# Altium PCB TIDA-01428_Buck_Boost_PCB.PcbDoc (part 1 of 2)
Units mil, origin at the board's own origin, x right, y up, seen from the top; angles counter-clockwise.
Board outline 4000 x 3000 mil, 2 copper layers (Top Layer, Bottom Layer), stack 62 mil thick; 127 components, 76 nets, 360 pads, 338 vias.
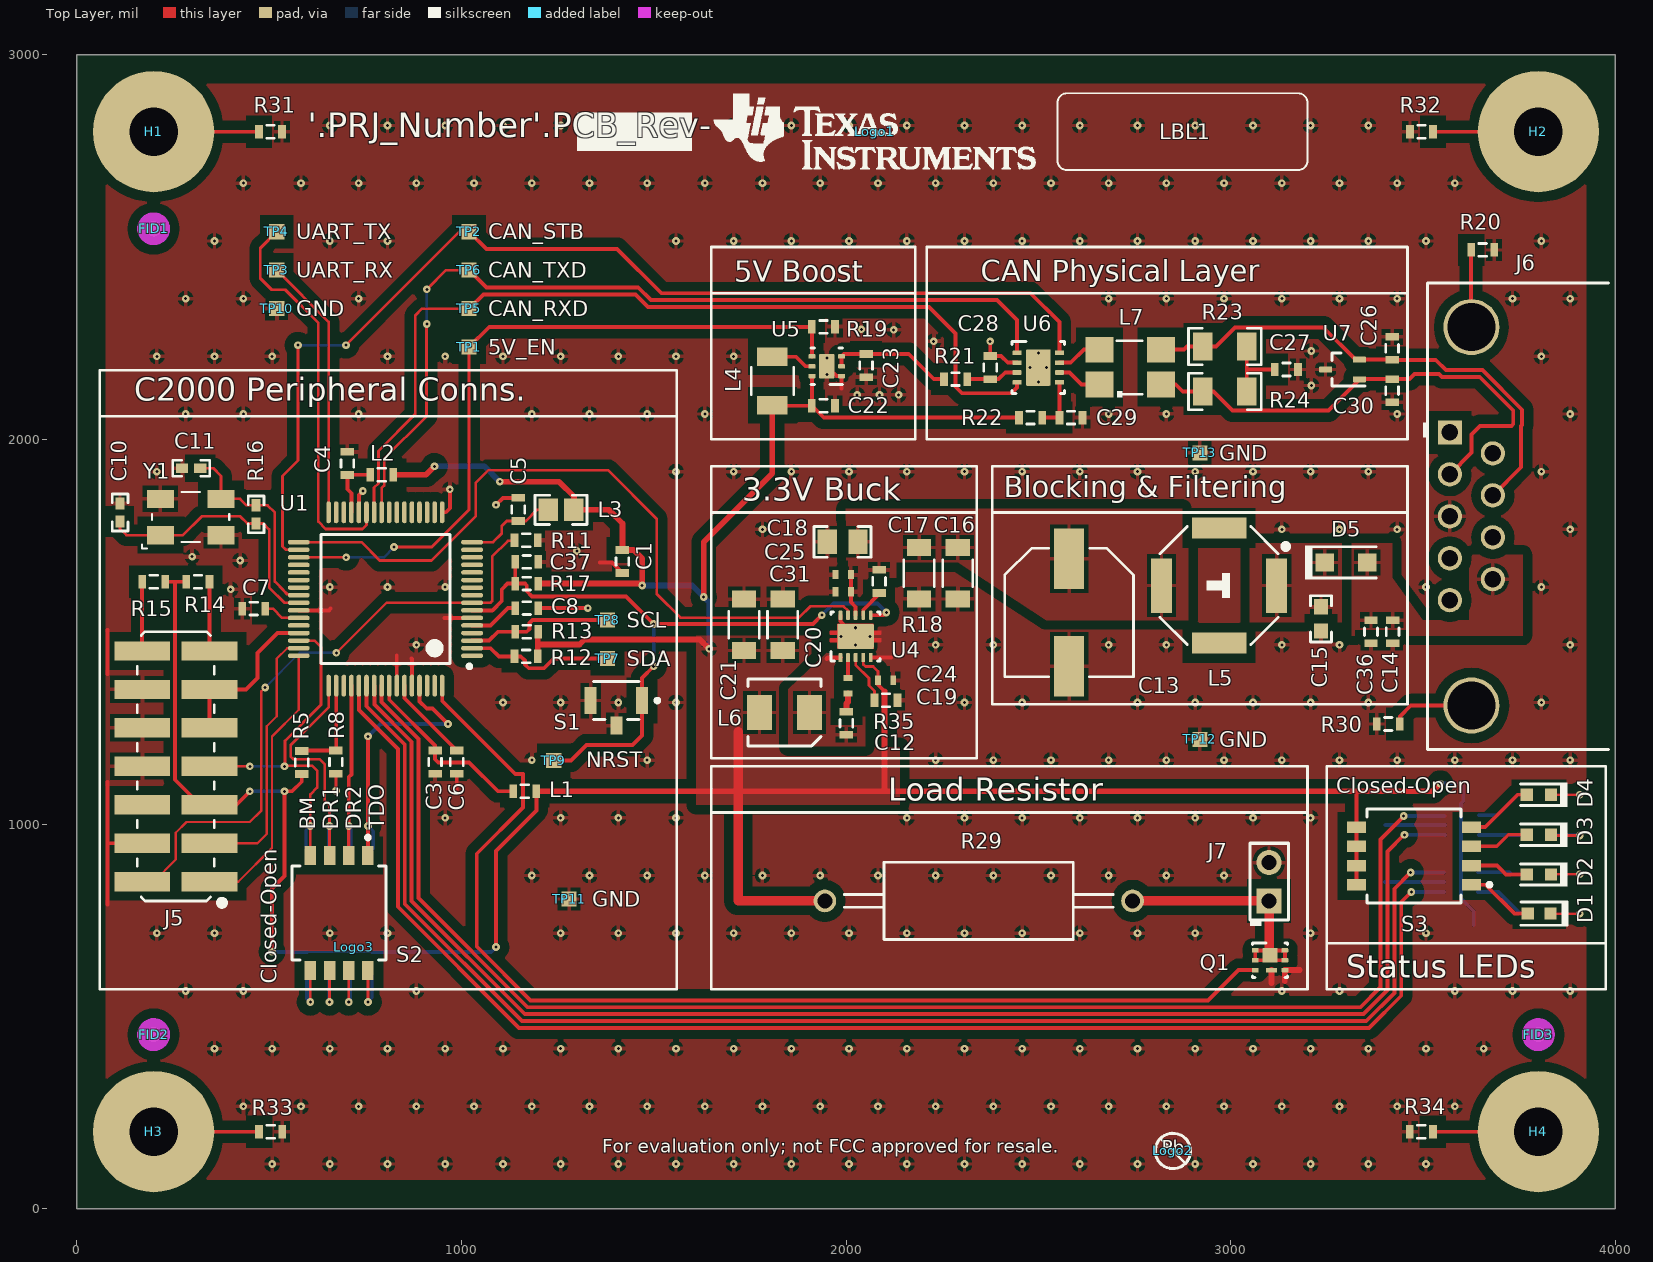
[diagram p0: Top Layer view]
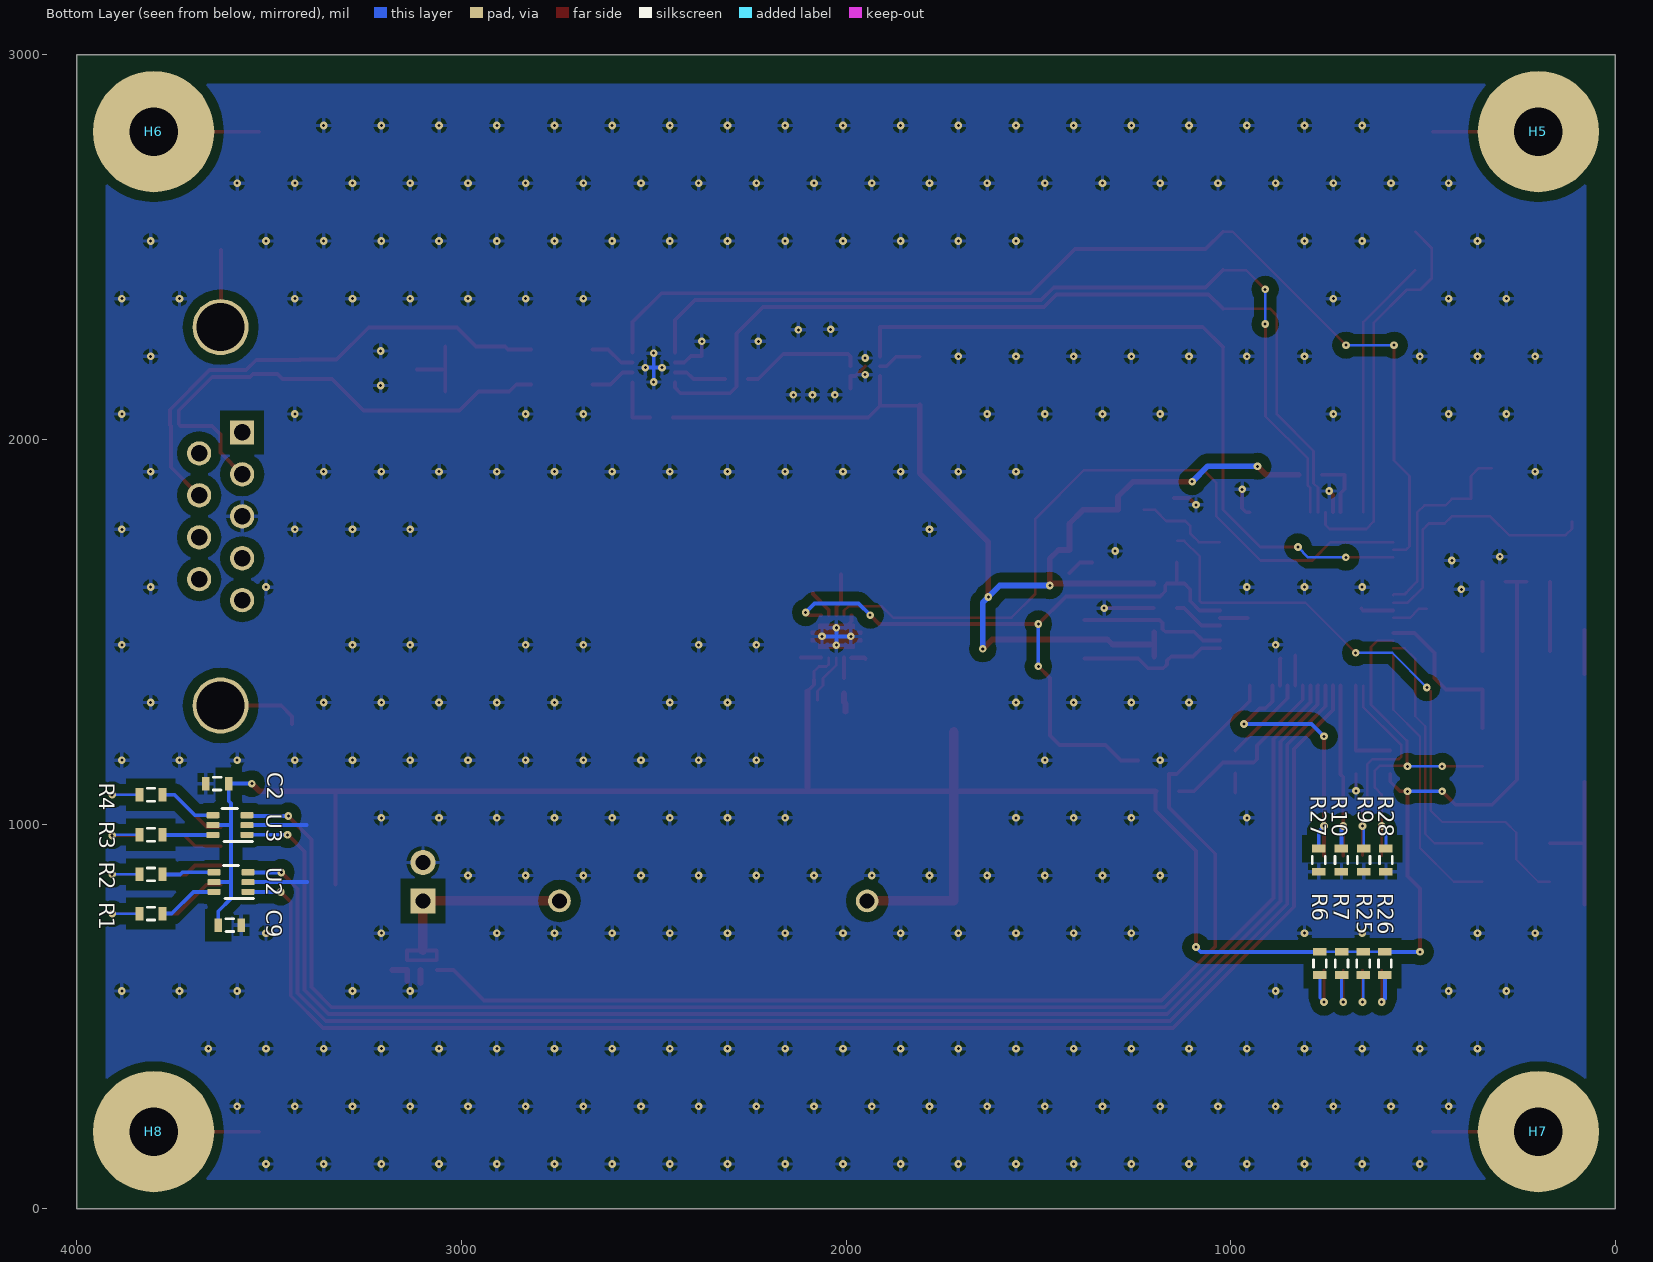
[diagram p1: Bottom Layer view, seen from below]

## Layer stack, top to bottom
Top Solder: solder mask 0.4, Solder Resist, Dk 3.5
Top Layer: signal copper 1.4
Dielectric1: core 59.2, FR-4, Dk 4.8
Bottom Layer: signal copper 1.4
Bottom Solder: solder mask 0.4, Solder Resist, Dk 3.5

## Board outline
0,0 0,3000 4000,3000 4000,0

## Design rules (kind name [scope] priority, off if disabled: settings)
AcuteAngle [All] p1: minimum=4.50000000000000E+0001 checktracksonly=FALSE
AssemblyTestPointUsage [All] p1: valid=2
BoardOutlineClearance BoardOutlineClearance_MountingHoles [OnCopper and InComponentClass('Mounting Holes')] p1: gap=40
BoardOutlineClearance BoardOutlineClearance_Poly [OnCopper and IsPoly] p2: gap=25
BoardOutlineClearance [OnCopper and Not InComponentClass('Logo') and not InComponentClass('FiducialMark') and not InRegion(1000,500,4000,800) and not InPoly] p3: gap=75
Clearance Clearance_Keepouts [((IsTrack Or IsArc) And Not InPoly) And IsFree and IsKeepOut vs ((IsTrack Or IsArc) And Not InPoly) And IsFree and IsKeepOut] p1: gap=0
Clearance Clearance_Poly [InPolygon] p2: gap=25 except(20: Fill-Fill)
Clearance [All] p3: gap=7.87
ComponentClearance ComponentClearance_MountingHoles_FiducialMarks [InComponentClass('Mounting Holes') vs InComponentClass('FiducialMark')] p1: gap=50 collisioncheckmode=3 verticalgap=10 showdistances=FALSE
ComponentClearance ComponentClearance_Shunt [InComponentClass('Header') vs InComponentClass('Shunt')] p2: gap=0 collisioncheckmode=3 verticalgap=0 showdistances=FALSE
ComponentClearance ComponentClearance_Logo [InComponentClass('Logo')] p3: gap=50 collisioncheckmode=3 verticalgap=10 showdistances=FALSE
ComponentClearance ComponentClearance_ScrewToNut [(HasFootprint('NY PMS 440 0025 PH')) vs (HasFootprint('Keystone_1902C'))] p4: gap=5 collisioncheckmode=3 verticalgap=10 showdistances=FALSE
ComponentClearance ComponentClearance_MountingHoles [InComponentClass('Mounting Holes')] p5: gap=100 collisioncheckmode=3 verticalgap=100000 showdistances=FALSE
ComponentClearance ComponentClearance_SmallPassives [HasFootprint('0201*') or HasFootprint('0402*') or HasFootprint('0508') or HasFootprint('0603*') or HasFootprint('0612') or HasFootprint('0805*') or HasFootprint('0815*') or HasFootprint('0830*') or HasFootprint('1206*') or HasFootprint('1210*') or HasFootprint('1808*') or HasFootprint('1812*') or HasFootprint('1825*') or HasFootprint('2010*') or HasFootprint('2220*') or HasFootprint('2225*') or HasFootprint('2512*') or HasFootprint('2728*') or HasFootprint('3518*') vs HasFootprint('0201*') or HasFootprint('0402*') or HasFootprint('0508') or HasFootprint('0603*') or HasFootprint('0612') or HasFootprint('0805*') or HasFootprint('0815*') or HasFootprint('0830*') or HasFootprint('1206*') or HasFootprint('1210*') or HasFootprint('1808*') or HasFootprint('1812*') or HasFootprint('1825*') or HasFootprint('2010*') or HasFootprint('2220*') or HasFootprint('2225*') or HasFootprint('2512*') or HasFootprint('2728*') or HasFootprint('3518*')] p6: gap=14.96 collisioncheckmode=3 verticalgap=10 showdistances=FALSE
ComponentClearance ComponentClearance_THtoSMT [IsThruComponent vs IsSMTComponent] p7: gap=40 collisioncheckmode=3 verticalgap=30 showdistances=FALSE
ComponentClearance ComponentClearance_THtoTH [IsThruComponent vs IsThruComponent] p8: gap=30 collisioncheckmode=3 verticalgap=30 showdistances=FALSE
ComponentClearance [All] p9: gap=30 collisioncheckmode=3 verticalgap=10 showdistances=FALSE
DiffPairsRouting [All] p1: maxlimit=100 minlimit=10 mostfreqgap=10 toplayer_minwidth=15 toplayer_maxwidth=15 toplayer_prefwidth=15 bottomlayer_minwidth=15 bottomlayer_maxwidth=15 bottomlayer_prefwidth=15 maxuncoupledlength=1000
FabricationTestPointUsage TestPointUsage [All] p1: valid=2 allowmultiple=FALSE
FabricationTestpoint Testpoint [All] p1: side=3 testpointundercomponent=TRUE minsize=40 maxsize=100 preferedsize=60 minholesize=0 maxholesize=40 preferedholesize=32 testpointgrid=1 allowsidetop=TRUE allowsidebottom=TRUE usegrid=TRUE gridtolerance=0.01
FanoutControl Fanout_LCC [IsLCC] p1: bgadir=Out bgaviamode=Centered fanoutstyle=Auto fanoutdirection=Alternating viagrid=1 // Fanout_LCC (Default Rule)
FanoutControl Fanout_BGA [IsBGA] p2: bgadir=Out bgaviamode=Centered fanoutstyle=Auto fanoutdirection=Alternating viagrid=1 // Fanout_BGA (Default Rule)
FanoutControl Fanout_Default [All] p4: bgadir=Out bgaviamode=Centered fanoutstyle=Auto fanoutdirection=Alternating viagrid=1 // Fanout_Default (Default Rule)
FanoutControl Fanout_Small [(CompPinCount < 5)] p5: bgadir=Out bgaviamode=Centered fanoutstyle=Auto fanoutdirection=OutThenIn viagrid=1 // Fanout_Small (Default Rule)
HoleSize [All] p1: absolutevalues=TRUE maxlimit=251 minlimit=7.87 maxpercent=80.000 minpercent=20.000
MinimumAnnularRing MinimumAnnularRing_ThermalPadVias [IsVia and InAnyComponent] p1: minimumring=5.91
MinimumAnnularRing [All] p2: minimumring=5
MinimumSolderMaskSliver MinimumSolderMaskSliver_Logo [InComponentClass('Logo') vs InComponentClass('Logo')] p1: minsoldermaskwidth=0.7
MinimumSolderMaskSliver [All] p2: minsoldermaskwidth=3.94
PlaneClearance [All] p1: clearance=15
PlaneConnect [All] p1: planeconnectstyle=Relief reliefexpansion=10 reliefentries=4 reliefconductorwidth=10 reliefairgap=8
PolygonConnect [All] p1: connectstyle=Relief reliefconductorwidth=10 reliefentries=4 polygonreliefangle="90 Angle" airgapwidth=10
RoutingVias ThermalPadVias [IsVia and InAnyComponent] p1: holewidth=7.87 width=19.68 viastyle="Through Hole" minholewidth=7.87 minwidth=19.68 maxholewidth=12.99 maxwidth=23.62
RoutingVias [All] p2: holewidth=16 width=34 viastyle="Through Hole" minholewidth=7.87 minwidth=20 maxholewidth=40 maxwidth=65
SilkToBoardRegionClearance [Not ((IsComment or IsDesignator) And (Hide <> 'False')) and not InRegion(1000,500,4000,800)] p1:
SilkToSilkClearance SilkToSilkClearance_Pb-FreeLogo [(HasFootprint('Pb-Free_Overlay_Medium') OR HasFootprint('Pb-Free_Overlay_Small')) vs (HasFootprint('Pb-Free_Overlay_Medium') OR HasFootprint('Pb-Free_Overlay_Small'))] p1: silktosilkclearance=0
SilkToSilkClearance [All] p2: silktosilkclearance=4
SilkToSolderMaskClearance SilkToComponentPadClearance [(IsPad or IsFill or IsRegion) and InAnycomponent] p1: minsilkscreentomaskgap=4.5 clearancetoexposedcopper=TRUE
SilkToSolderMaskClearance "Silk to Solder Mask Opening" [All] p2: minsilkscreentomaskgap=4 clearancetoexposedcopper=FALSE
SolderMaskExpansion [All] p1: expansion=1.97
Width [All] p1: maxlimit=100 minlimit=6 preferedwidth=10 checkconnectedcopper=TRUE
14 further rules are at their usual default settings.

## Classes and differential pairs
component class TIDA-01428_Buck_Boost_MCU: C1 C2 C3 C4 C5 C6 C7 C8 C9 C10 C11 C37 D1 D2 D3 D4 J5 L1 L2 L3 R1 R2 R3 R4 R5 R6 R7 R8 R9 R10 R11 R12 R13 R14 R15 R16 R25 R26 R27 R28 S1 S2 S3 TP1 TP2 TP3 TP4 TP5 TP6 TP7 TP8 TP9 TP10 TP11 TP12 TP13 U1 U2 U3 Y1
component class TIDA-01428_Buck_Boost_Main: C12 C13 C14 C15 C16 C17 C18 C19 C20 C21 C22 C23 C24 C25 C26 C27 C28 C29 C30 C31 C36 D5 J6 J7 L4 L5 L6 L7 Q1 R17 R18 R19 R20 R21 R22 R23 R24 R29 R30 R35 U4 U5 U6 U7
component class Header: J5 J7
component class "Mounting Holes": H1 H2 H3 H4
component class Logo: Logo1
component class TIDA-01428_Buck_Boost_Hardware: FID1 FID2 FID3 H1 H2 H3 H4 H5 H6 H7 H8 LBL1 Logo1 Logo2 Logo3 R31 R32 R33 R34 ZZ1 ZZ2 ZZ3 ZZ4
component class FiducialMark: FID1 FID2 FID3
component class AssemblyNote: ZZ1 ZZ2 ZZ3 ZZ4
component class Label: LBL1

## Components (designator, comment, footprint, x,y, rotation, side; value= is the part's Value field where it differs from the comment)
C1 "C1608X5R1A105K080AC" 0603S 1418.75,1682.5 r270 top
C2 "06033C104JAT2A" 0603S 3635,1105 r0 bottom
C3 "C0603C225K9PACTU" 0603S 931.5,1160.91 r270 top
C4 "C0603C225K9PACTU" 0603S 703.75,1937.5 r90 top
C5 "C0603C225K9PACTU" 0603S 1148,1818 r90 top
C6 "C0603C225K9PACTU" 0603S 987.81,1160.91 r270 top
C7 "C0603C225K9PACTU" 0603S 460,1560 r180 top
C8 "C0603C225K9PACTU" 0603S 1170,1561.31 r0 top
C9 "06033C104JAT2A" 0603S 3602,737 r180 bottom
C10 "GRM1555C1E360JA01D" 0402 112.5,1810 r90 top
C11 "GRM1555C1E360JA01D" 0402 297.5,1925 r180 top
C12 "GCM188R71H104KA57D" 0603S 2001,1262 r270 top
C13 "EEE-FK1J470P" SM_RADIAL_F 2580,1550 r270 top
C14 "GCJ188R72A104KA01D" 0603S 3421.31,1500 r270 top
C15 "GRM188R61H105KAALD" 0603 3235.04,1533.19 r270 top
C16 "GRM31CR71H475KA12L" 1206_180 2290.4,1652 r270 top
C17 "GRM31CR71H475KA12L" 1206_180 2190,1652 r270 top
C18 "C2012X7R2A104K125AA" 0805_HV 1991,1733.6 r180 top
C19 "GCM188R71C105KA64D" 0603S 2103.98,1321.89 r0 top
C20 "GRM31CR71C106KAC7L" 1206_180 1835.36,1517.89 r90 top
C21 "GRM31CR71C106KAC7L" 1206_180 1734.96,1517.89 r90 top
C22 "C0603C225K8PACTU" 0603S 1941.25,2087.5 r0 top
C23 "C0603C475K8PACTU" 0603S 2052.31,2191.86 r270 top
C24 "C1005X7R1C103K050BA" 0402S 2102.96,1373.97 r0 top
C25 "CGA2B3X7S2A152K050BB" 0402S 1993,1648.5 r180 top
C26 "GRM1885C1H560JA01D" 0603S 3420,2236.69 r90 top
C27 "GCM188R71H472KA37D" 0603S 3145,2181.69 r0 top
C28 "06033C104JAT2A" 0603S 2375,2186.69 r90 top
C29 "06033C104JAT2A" 0603S 2585,2056.69 r0 top
C30 "GRM1885C1H560JA01D" 0603S 3420,2126.69 r270 top
C31 "C0402C122J5GACTU" 0402S 1993,1604 r180 top
C36 "UMK107AB7105KA-T" 0603S 3365,1500 r270 top
C37 "06031C103JAT2A" 0603S 1170,1681.31 r0 top
D1 "LB Q39G-L2N2-35-1" "LB Q39G_BLUE" 3802,767 r0 top
D2 "150060VS75000" WL-SMCW_GREEN 3801.56,868.99 r180 top
D3 "150060RS75000" WL-SMCW_RED 3801.56,972 r180 top
D4 "150060YS75000" WL-SMCW_YELLOW 3801.56,1076 r180 top
D5 "SS24FL" SOD-123F 3300,1680 r0 top
FID1 "Fiducial" Fiducial10-20 200,2547.67 r0 top
FID2 "Fiducial" Fiducial10-20 200,452.33 r0 top
FID3 "Fiducial" Fiducial10-20 3800,452.33 r0 top
H1 "NY PMS 440 0025 PH" "NY PMS 440 0025 PH" 200,2800 r0 top locked
H2 "NY PMS 440 0025 PH" "NY PMS 440 0025 PH" 3800,2800 r0 top locked
H3 "NY PMS 440 0025 PH" "NY PMS 440 0025 PH" 200,200 r0 top locked
H4 "NY PMS 440 0025 PH" "NY PMS 440 0025 PH" 3800,200 r0 top locked
H5 "1902C" Keystone_1902C 200,2800 r180 bottom locked
H6 "1902C" Keystone_1902C 3800,2800 r180 bottom locked
H7 "1902C" Keystone_1902C 200,200 r180 bottom locked
H8 "1902C" Keystone_1902C 3800,200 r180 bottom locked
J5 "0015912140" Molex_0015912140 257.5,1150 r90 top
J6 "1734354-1" TE_1734354-1 4000,1800 r0 top locked
J7 "5-146278-2" TE_5-146278-2 3100,850 r90 top locked
L1 "742792602" 0603S 1165,1085 r0 top
L2 "742792602" 0603S 793,1908 r0 top
L3 "BLM21PG221SN1D" 0805 1259,1817 r0 top
L4 "NLCV32T-1R0M-PF" NLCV32 1808.48,2151.86 r90 top
L5 "7440690010" WE-TPC-8015 2970,1620 r270 top
L6 "MPI4040R3-4R7-R" MPI4040R3 1840,1290 r180 top
L7 "B82789C0104H001" SIMDAD_1812 2738.89,2188.08 r90 top
LBL1 "Size: 0.65\" x 0.20 \"" Label_650x200 2875,2800 r0 top
Logo1 "Texas Instruments" TI_Stacked_Overlay_Small 2075,2800 r0 top
Logo2 "Pb-Free Symbol" Pb-Free_Overlay_Small 2850,150 r0 top
Logo3 "FCC disclaimer" FCC_disclaimer 720,680 r0 top
Q1 "CSD17313Q2Q1" DQK0006C 3102.61,645.78 r0 top
R1 "RC0603FR-0716R9L" 0603S 3807.07,767 r0 bottom
R2 "CRCW060328R0FKEA" 0603S 3807.07,869 r0 bottom
R3 "CRCW060328R0FKEA" 0603S 3807.07,972 r0 bottom
R4 "CRCW060328R0FKEA" 0603S 3807.07,1076.01 r0 bottom
R5 "CRCW0603100KFKEA" 0603S 585,1160 r270 top
R6 "CRCW06031K00FKEA" 0603S 767.8,637.51 r90 bottom
R7 "CRCW06031K00FKEA" 0603S 711.49,637.51 r90 bottom
R8 "CRCW0603100KFKEA" 0603S 673.81,1160.91 r90 top
R9 "CRCW060310K0FKEA" 0603S 654.19,906.14 r90 bottom
R10 "CRCW060310K0FKEA" 0603S 711.88,906.14 r90 bottom
R11 "RC0603FR-072K2L" 0603S 1168.31,1737.62 r180 top
R12 "CRCW060310K0JNEA" 0603S 1168.31,1435.61 r0 top
R13 "CRCW060310K0JNEA" 0603S 1170,1500 r0 top
R14 "CRCW06034K70JNEA" 0603S 315,1630 r180 top
R15 "CRCW06034K70JNEA" 0603S 200,1630 r0 top
R16 "CRCW04021M00JNED" 0402 466.39,1805 r270 top
R17 "RC0603FR-072K2L" 0603S 1170,1625 r180 top
R18 "CRCW0603100KFKEA" 0603S 2085.96,1630.84 r90 top
R19 "CRCW0603100KFKEA" 0603S 1941.25,2292.5 r180 top
R20 "ERJ-3GEY0R00V" 0603S 3655.26,2492.57 r0 top
R21 "ERJ-3GEY0R00V" 0603S 2285,2156.69 r0 top
R22 "ERJ-3GEY0R00V" 0603S 2480,2056.69 r0 top
R23 "CRCW120660R4FKEA" 1206 2985,2241.69 r180 top
R24 "CRCW120660R4FKEA" 1206 2985,2124.45 r0 top
R25 "RC0603FR-07820RL" 0603S 655.18,637.51 r90 bottom
R26 "RC0603FR-07820RL" 0603S 598.87,637.51 r90 bottom
R27 "RC0603FR-073K3L" 0603S 771,906.14 r90 bottom
R28 "RC0603FR-073K3L" 0603S 596.18,906.14 r90 bottom
R29 "PNP300JR-73-4R7" PNP300 2345,800 r180 top
R30 "ERJ-3GEY0R00V" 0603S 3409.85,1260 r180 top
R31 "ERJ-3GEY0R00V" 0603S 503.75,2800 r0 top
R32 "ERJ-3GEY0R00V" 0603S 3496.25,2800 r180 top
R33 "ERJ-3GEY0R00V" 0603S 504.01,200 r0 top
R34 "ERJ-3GEY0R00V" 0603S 3495.99,200 r180 top
R35 "ERJ-2BQFR47X" 0402S 2005,1359.26 r270 top
S1 "B3U-1100P" SW_B3U-1100P 1403,1321 r180 top
S2 "1571983-5" SW_1571983-5 682.18,768.82 r270 top
S3 "1571983-5" SW_1571983-5 3477,917 r180 top
TP1 "PAD_1MM_SQUARE" PAD_1MM_SQUARE 1020,2240 r0 top
TP2 "PAD_1MM_SQUARE" PAD_1MM_SQUARE 1020,2540 r0 top
TP3 "PAD_1MM_SQUARE" PAD_1MM_SQUARE 520,2440 r0 top
TP4 "PAD_1MM_SQUARE" PAD_1MM_SQUARE 520,2540 r0 top
TP5 "PAD_1MM_SQUARE" PAD_1MM_SQUARE 1020,2340 r0 top
TP6 "PAD_1MM_SQUARE" PAD_1MM_SQUARE 1020,2440 r0 top
TP7 "PAD_1MM_SQUARE" PAD_1MM_SQUARE 1380,1430 r90 top
TP8 "PAD_1MM_SQUARE" PAD_1MM_SQUARE 1380,1530 r90 top
TP9 "PAD_1MM_SQUARE" PAD_1MM_SQUARE 1240,1165 r0 top
TP10 "PAD_1MM_SQUARE" PAD_1MM_SQUARE 520,2340 r90 top
TP11 "PAD_1MM_SQUARE" PAD_1MM_SQUARE 1280,805 r90 top
TP12 "PAD_1MM_SQUARE" PAD_1MM_SQUARE 2920,1220 r90 top
TP13 "PAD_1MM_SQUARE" PAD_1MM_SQUARE 2920,1965 r90 top
U1 "TMS320F28030PAGQ" PAG0064A_N 802.5,1585.07 r180 top locked
U2 "SN74LVC2G06QDCKRQ1" DCK0006A_N 3599,849 r0 bottom
U3 "SN74LVC2G06QDCKRQ1" DCK0006A_N 3601.91,997.19 r0 bottom
U4 "LM53601NQDSXRQ1" DSX0010A 2025,1487.64 r90 top
U5 "TPS61240IDRVRQ1" DRV0006A 1950,2190 r180 top
U6 "TCAN1042HGVDRBQ1" DRB0008F 2500,2186.69 r0 top
U7 "TPD2E007DCKR" DCK0003A_N 3291.15,2181.69 r180 top
Y1 "ABM3B-20.000MHZ-10-1-U-T" ABRACON_ABM3B 296.23,1798.16 r90 top
ZZ1 "This Assembly Note is for PCB labels only" AssemblyNoteLabel 185,3938 r0 top
ZZ2 "These assemblies are ESD sensitive, ESD precautions shall be observed." AssemblyNote 185,3829.11 r0 top
ZZ3 "These assemblies must be clean and free from flux and all contaminants. Use of no clean flux is not acceptable." AssemblyNote 185,3740.56 r0 top
ZZ4 "These assemblies must comply with workmanship standards IPC-A-610 Class 2, unless otherwise specified." AssemblyNote 185,3652 r0 top

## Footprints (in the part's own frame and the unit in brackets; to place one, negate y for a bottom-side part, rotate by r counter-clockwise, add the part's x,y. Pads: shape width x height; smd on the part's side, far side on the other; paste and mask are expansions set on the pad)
0402 [mm] "0402 from SM-752 data"
  rect 0.8x0.6 smd: 1(-0.6,0) 2(0.6,0)
  silkscreen extent -1.22,-0.52 1.22,0.52, body extent -0.55,-0.3 0.55,0.3, height 0.6
0402S [mil] "Based on C0402S footprint from PADS legacy"
  rect 15x24 smd: 1(-20,0) 2(20,0)
  body extent -22,-12 22,12, height 24
0603 [mm] "0603 from SM-752 data"
  rect 1x0.95 smd: 1(-0.8,0) 2(0.8,0)
  silkscreen extent -1.52,-0.69 1.52,0.69, body extent -0.87,-0.47 0.87,0.47, height 1
0603S [mil]
  rect 20x35 smd: 1(-30,0) 2(30,0)
  silkscreen extent -10,-17 10,17, body extent -34,-19 34,19, height 39
0805 [mm] "0805 from SM-752 data"
  rect 1.3x1.5 smd: 1(-0.85,0) 2(0.85,0)
  silkscreen extent -1.72,-0.97 1.72,0.97, body extent -1.1,-0.72 1.1,0.72, height 1.45
0805_HV [mil] "0805 with 30mil clearance between pads"
  rect 50x63 smd: 1(-40,0) 2(40,0)
  silkscreen extent -74,-40 74,40, body extent -43,-29 43,29, height 57
1206 [mm] "1206 from SM-752 data"
  rect 1.3x1.85 smd: 1(-1.45,0) 2(1.45,0)
  silkscreen extent -2.4,-1.21 2.4,1.21, body extent -1.7,-0.9 1.7,0.9, height 1.35
1206_180 [mm] "1206_180"
  rect 1.1x1.6 smd: 1(-1.7,0) 2(1.7,0)
  silkscreen extent -0.9,-1 0.9,1, body extent -1.75,-0.95 1.75,0.95, height 1.8
ABRACON_ABM3B [mm] "ABRACON"
  rect 1.2x1.8 smd: 1(-1.2,2) 2(-1.2,-2) 3(1.2,-2) 4(1.2,2)
  silkscreen extent -2.08,-2.55 1.65,3.22, body extent -1.65,-2.55 1.65,2.55, height 1.12
AssemblyNote [mil] "Assembly Note"
AssemblyNoteLabel [mil] "Assembly Note for PCB Labels"
DCK0003A_N [mm] "SOT23, 3-Leads, Body 2.0x1.25mm, Pitch 0.65mm, Lead Span 2.1mm, IPC Medium Density"
  rrect25% 0.85x0.4 smd: 1(-1.125,0.65) 2(-1.125,-0.65) 3(1.125,0)
  silkscreen extent -1.48,-1.1 0.7,1.1, body extent -1.06,-1 1.06,1, height 1.1
DCK0006A_N [mm] "SOT23, 6-Leads, Body 2x1.3mm, Pitch 0.65mm, Lead Span 2.1mm, IPC Medium Density"
  rrect25% 0.85x0.4 smd: 1(-1.125,0.65) 2(-1.125,0) 3(-1.125,-0.65) 4(1.125,-0.65) 5(1.125,0) 6(1.125,0.65)
  silkscreen extent -1.5,-1.09 0.51,1.09, body extent -1.14,-1 1.14,1, height 0.95
DQK0006C [mm] "WSON"
  rrect12% 0.9x0.86 on Top Paste: 0(0,0.325)
  rrect34% 0.7x0.29 on Top Paste: 0(0.095,-0.65)
  rrect33% 0.45x0.3 smd: 1(-0.975,0.65) 2(-0.975,0) 3(-0.975,-0.65) 4(0.975,-0.65) 5(0.975,0) 6(0.975,0.65)
  rrect33% 0.75x0.3 smd paste-0.15: 7(0.095,-0.65)
  rrect11% 1x0.95 smd paste-0.5: 8(0,0.325)
  silkscreen extent -1.15,-1.15 1.15,1.15, body extent -1,-1 1,1, height 0.82
DRB0008F [mm] "SON, 8-Leads, Body 3x3mm, Pitch 0.65mm, Thermal Pad 2.4x1.6mm, TI Recommended"
  rrect33% 0.6x0.3 smd: 1(-1.4,0.975) 2(-1.4,0.325) 3(-1.4,-0.325) 4(-1.4,-0.975) 5(1.4,-0.975) 6(1.4,-0.325) 7(1.4,0.325) 8(1.4,0.975)
  rrect9% 1.47x1.07 on Top Paste: 9(0,-0.635) 9(0,0.635)
  rrect6% 1.6x2.4 smd paste-1.2: 9(0,0)
  silkscreen extent -1.73,-1.73 1.73,1.73, body extent -1.5,-1.5 1.5,1.5, height 0.77
DRV0006A [mm] "SON, 6-Leads, Body 2x2mm, Pitch 0.65mm, Thermal Pad 1.6x1mm, TI Recommended"
  rrect33% 0.45x0.3 smd: 1(-0.975,0.65) 2(-0.975,0) 3(-0.975,-0.65) 4(0.975,-0.65) 5(0.975,0) 6(0.975,0.65)
  rrect14% 1x0.7 on Top Paste: 7(0,0.45) 7(0,-0.45)
  rrect10% 1x1.6 smd paste-0.5: 7(0,0)
  silkscreen extent -1.05,-1.2 1.05,1.2, body extent -1.05,-1.05 1.05,1.05, height 0.81
DSX0010A [mm] "SON, 10-Leads, Body 3x3 mm, Pitch 0.5mm"
  rrect40% 0.6x0.25 smd: 1(-1.4,1) 2(-1.4,0.5) 3(-1.4,0) 4(-1.4,-0.5) 5(-1.4,-1) 6(1.4,-1) 7(1.4,-0.5) 8(1.4,0) 9(1.4,0.5) 10(1.4,1)
  rrect40% 0.25x0.34 on Top Paste: 11(-0.25,1.53) 11(-0.25,-1.53) 11(0.25,1.53) 11(0.25,-1.53)
  rrect9% 1.5x1.06 on Top Paste: 11(0,0.63) 11(0,-0.63)
  rrect12% 1.65x2.4 smd paste-1 mask-2: 11(0,0)
  Top Layer region: -0.775,-1.2 -0.375,-1.2 -0.375,-1.65 -0.371,-1.669 -0.36,-1.685 -0.344,-1.696 -0.325,-1.7 -0.325,-1.7 -0.325,-1.7 -0.175,-1.7 -0.175,-1.7 -0.156,-1.696 -0.14,-1.685 -0.129,-1.669 -0.125,-1.65 -0.125,-1.65 -0.125,-1.65 -0.125,-1.2 0.125,-1.2 0.125,-1.65 0.129,-1.669 0.14,-1.685 0.156,-1.696 0.175,-1.7 0.175,-1.7 0.175,-1.7 0.325,-1.7 0.325,-1.7 0.344,-1.696 0.36,-1.685 0.371,-1.669 0.375,-1.65 0.375,-1.65 0.375,-1.2 0.775,-1.2 0.794,-1.196 0.81,-1.185 0.821,-1.169 0.825,-1.15 0.825,-1.15 0.825,1.15 0.821,1.169 0.81,1.185 0.794,1.196 0.775,1.2 0.775,1.2 0.375,1.2 0.375,1.65 0.371,1.669 0.36,1.685 0.344,1.696 0.325,1.7 0.325,1.7 0.175,1.7 0.156,1.696 0.14,1.685 0.129,1.669 0.125,1.65 0.125,1.65 0.125,1.2 -0.125,1.2 -0.125,1.65 -0.125,1.65 -0.129,1.669 -0.14,1.685 -0.156,1.696 -0.175,1.7 -0.175,1.7 -0.325,1.7 -0.344,1.696 -0.36,1.685 -0.371,1.669 -0.375,1.65 -0.375,1.65 -0.375,1.2 -0.775,1.2 -0.794,1.196 -0.81,1.185 -0.821,1.169 -0.825,1.15 -0.825,1.15 -0.825,-1.15 -0.821,-1.169 -0.81,-1.185 -0.794,-1.196 -0.775,-1.2
  silkscreen extent -1.63,-1.63 1.63,1.63, body extent -1.5,-1.5 1.5,1.5, height 0.8
FCC_disclaimer [mil]
Fiducial10-20 [mm]
  round 1 smd mask+0.5: 1(0,0)
  Top Layer keep-out circle w1.178: c0,0 r0.5
Keystone_1902C [mil] "Hex Standoff, 4-40 threaded, nylon"
  body extent -145,-126 146,126, height 501
Label_650x200 [mil] "Thermal Transfer Label"
  silkscreen extent -325,-100 325,100, body extent -325,-100 325,100, height 1
"LB Q39G_BLUE" [mm] "OSRAM"
  rect 0.8x0.8 smd: 1(-0.75,0) 2(0.75,0)
  silkscreen extent 1.5,-0.43 1.73,0.57, body extent -0.85,-0.45 0.85,0.45, height 0.4
Molex_0015912140 [mil] "MOLEX"
  rect 50x144.88 smd: 1(-300,-87.5) 2(-300,87.5) 3(-200,-87.5) 4(-200,87.5) 5(-100,-87.5) 6(-100,87.5) 7(0,-87.5) 8(0,87.5) 9(100,-87.5) 10(100,87.5) 11(200,-87.5) 12(200,87.5) 13(300,-87.5) 14(300,87.5)
  silkscreen extent -363,-128 350,100, body extent -349,-137 351,138, height 379
MPI4040R3 [mm] "Coiltronics"
  rect 1.65x2.3 smd: 1(-1.65,0) 2(1.65,0)
  silkscreen extent -2.4,-2.2 2.4,2.2, body extent -2.35,-2.15 2.35,2.15, height 1.86
NLCV32 [mm] "TDK"
  rect 1.2x2 smd: 1(-1.6,0) 2(1.6,0)
  silkscreen extent -0.9,-1.4 0.9,1.4, body extent -1.7,-1.35 1.7,1.35, height 2.4
"NY PMS 440 0025 PH" [mm] "4-40 nylon screw and mounting hole"
  round 8 hole 3.2: 1(0,0)
  body extent -3.3,-3.3 3.3,3.3, height 2.69
PAD_1MM_SQUARE [mm]
  rect 1x1 smd: 1(0,0)
PAG0064A_N [mm] "Thin QFP, 64-Leads, Body 10x10mm, Pitch 0.5mm, IPC Medium Density"
  oval 1.45x0.3 smd: 1(-5.725,3.75) 2(-5.725,3.25) 3(-5.725,2.75) 4(-5.725,2.25) 5(-5.725,1.75) 6(-5.725,1.25) 7(-5.725,0.75) 8(-5.725,0.25) 9(-5.725,-0.25) 10(-5.725,-0.75) 11(-5.725,-1.25) 12(-5.725,-1.75) 13(-5.725,-2.25) 14(-5.725,-2.75) 15(-5.725,-3.25) 16(-5.725,-3.75) 33(5.725,-3.75) 34(5.725,-3.25) 35(5.725,-2.75) 36(5.725,-2.25) 37(5.725,-1.75) 38(5.725,-1.25) 39(5.725,-0.75) 40(5.725,-0.25) 41(5.725,0.25) 42(5.725,0.75) 43(5.725,1.25) 44(5.725,1.75) 45(5.725,2.25) 46(5.725,2.75) 47(5.725,3.25) 48(5.725,3.75)
  oval 0.3x1.45 smd: 17(-3.75,-5.725) 18(-3.25,-5.725) 19(-2.75,-5.725) 20(-2.25,-5.725) 21(-1.75,-5.725) 22(-1.25,-5.725) 23(-0.75,-5.725) 24(-0.25,-5.725) 25(0.25,-5.725) 26(0.75,-5.725) 27(1.25,-5.725) 28(1.75,-5.725) 29(2.25,-5.725) 30(2.75,-5.725) 31(3.25,-5.725) 32(3.75,-5.725) 49(3.75,5.725) 50(3.25,5.725) 51(2.75,5.725) 52(2.25,5.725) 53(1.75,5.725) 54(1.25,5.725) 55(0.75,5.725) 56(0.25,5.725) 57(-0.25,5.725) 58(-0.75,5.725) 59(-1.25,5.725) 60(-1.75,5.725) 61(-2.25,5.725) 62(-2.75,5.725) 63(-3.25,5.725) 64(-3.75,5.725)
  silkscreen extent -5.68,-4.25 4.25,4.57, body extent -6,-6 6,6, height 1.09
Pb-Free_Overlay_Small [mil]
  silkscreen extent -46,-46 46,46
PNP300 [mm] "yageo"
  round 1.5 hole 1: 1(-10.16,0) 2(10.16,0)
  silkscreen extent -8.89,-2.55 8.89,2.55, body extent -10.58,-2.54 10.58,2.55, height 5.08
SIMDAD_1812 [mm] "EPCOS"
  rect 1.7x1.85 smd: 1(-1.15,2.025) 2(-1.15,-2.025) 3(1.15,-2.025) 4(1.15,2.025)
  silkscreen extent -2,-0.8 1.75,0.9, body extent -1.75,-2.6 1.75,2.6, height 3.01
SM_RADIAL_F [mm] "8 x 10.2mm:  Panasonic F"
  rect 4x2 smd: 1(-3.55,0) 2(3.55,0)
  silkscreen extent -4.25,-4.25 4.25,4.25, body extent -4.25,-4.25 4.25,4.25, height 10.5
SOD-123F [mm] "NXP recommended land pattern"
  rect 1.2x1.2 smd paste-0.05: 1(-1.4,0) 2(1.4,0)
  silkscreen extent -2.72,-1.12 2.01,1.12, body extent -1.8,-0.85 1.8,0.85, height 1.2
SW_1571983-5 [mm] "SMD, 8-Leads, Pitch 1.27mm"
  rect 1.27x0.76 smd: 1(-3.795,1.905) 2(-3.795,0.635) 3(-3.795,-0.635) 4(-3.795,-1.905) 5(3.795,-1.905) 6(3.795,-0.635) 7(3.795,0.635) 8(3.795,1.905)
  silkscreen extent -5.1,-3.1 3.1,3.1, body extent -4.06,-3.1 4.06,3.1, height 2.31
SW_B3U-1100P [mm] "SMD, 3-Leads, Body 3x2.5mm"
  rect 0.8x1.8 smd: 1(-1.7,0) 2(1.7,0)
  rect 0.8x1.2 smd: 3(0,1.65)
  silkscreen extent -2.83,-1.25 1.5,1.25, body extent -2,-1.25 2,1.9, height 1.6
TE_5-146278-2 [mm] "TE CONNECTIVITY"
  rect 1.65x1.65 hole 1: 1(-1.27,0)
  round 1.65 hole 1: 2(1.27,0)
  silkscreen extent -2.92,-1.27 2.54,1.27, body extent -2.41,-1.17 2.41,1.17, height 8.13
TE_1734354-1 [mm] "Receptacle, D-Sub, 9 Position, R/A, TH"
  rect 1.6x1.6 hole 1.09: 1(-10.92,5.54)
  round 1.6 hole 1.09: 2(-10.92,2.77) 3(-10.92,0) 4(-10.92,-2.77) 5(-10.92,-5.54) 6(-8.08,4.155) 7(-8.08,1.385) 8(-8.08,-1.385) 9(-8.08,-4.155)
  round 3.7 hole 3.18: 10(-9.5,12.495) 11(-9.5,-12.495)
  silkscreen extent -12.68,-15.4 -0.43,15.4, body extent -12.4,-15.4 6.02,15.4, height 12.5
TI_Stacked_Overlay_Small [mil]
  silkscreen extent -418,-98 418,98
WE-TPC-8015 [mm] "WURTH ELEKTRONIK"
  rect 3.6x1.4 smd: 1(0,3.8) 3(0,-3.8)
  rect 1.4x3.6 smd: 2(3.8,0) 4(-3.8,0)
  silkscreen extent -3.9,-3.9 3.9,4.58, body extent -4.15,-4.15 4.15,4.15, height 1.51
WL-SMCW_GREEN [mm] "WURTH"
  rect 0.8x0.8 smd: 1(-0.8,0) 2(0.8,0)
  silkscreen extent -1.9,-0.8 1.2,0.8, body extent -0.85,-0.45 0.85,0.45, height 0.8
WL-SMCW_RED [mm] "WURTH"
  rect 0.8x0.8 smd: 1(-0.8,0) 2(0.8,0)
  silkscreen extent -1.9,-0.8 1.2,0.8, body extent -0.85,-0.45 0.85,0.45, height 0.8
WL-SMCW_YELLOW [mm] "WURTH"
  rect 0.8x0.8 smd: 1(-0.8,0) 2(0.8,0)
  silkscreen extent -1.9,-0.8 1.2,0.8, body extent -0.85,-0.45 0.85,0.45, height 0.8

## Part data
C1: "CAP, CERM, 1 µF, 10 V, +/- 10%, X5R, 0603"
C2 C9 C28 C29: "CAP, CERM, 0.1 µF, 25 V, +/- 5%, X7R, 0603"
C3 C4 C5 C6 C7 C8: "CAP, CERM, 2.2 µF, 6.3 V, +/- 10%, X5R, 0603"
C10 C11: "CAP, CERM, 36 pF, 25 V, +/- 5%, C0G/NP0, 0402"
C12: "CAP, CERM, 0.1 µF, 50 V, +/- 10%, X7R, 0603"
C13: "CAP, AL, 47 µF, 63 V, +/- 20%, 0.65 ohm, AEC-Q200 Grade 2, SMD"
C14: "CAP, CERM, 0.1 µF, 100 V, +/- 10%, X7R, AEC-Q200 Grade 1, 0603"
C15: "CAP, CERM, 1 µF, 50 V, +/- 10%, X5R, 0603"
C16 C17: "CAP, CERM, 4.7 µF, 50 V, +/- 10%, X7R, 1206"
C18: "CAP, CERM, 0.1 µF, 100 V, +/- 10%, X7R, 0805"
C19: "CAP, CERM, 1 µF, 16 V, +/- 10%, X7R, AEC-Q200 Grade 1, 0603"
C20 C21: "CAP, CERM, 10 µF, 16 V, +/- 10%, X7R, 1206"
C22: "CAP, CERM, 2.2 µF, 10 V, +/- 10%, X5R, 0603"
C23: "CAP, CERM, 4.7 µF, 10 V, +/- 10%, X5R, 0603"
C24: "CAP, CERM, 0.01 µF, 16 V, +/- 10%, X7R, 0402"
C25: "CAP, CERM, 1500 pF, 100 V, +/- 10%, X7S, AEC-Q200 Grade 1, 0402"
C26 C30: "CAP, CERM, 56 pF, 50 V, +/- 5%, C0G/NP0, 0603"
C27: "CAP, CERM, 4700 pF, 50 V, +/- 10%, X7R, AEC-Q200 Grade 1, 0603"
C31: "CAP, CERM, 1200 pF, 50 V, +/- 5%, C0G/NP0, 0402"
C36: "CAP, CERM, 1 µF, 50 V, +/- 10%, X7R, 0603"
C37: "CAP, CERM, 0.01 µF, 100 V, +/- 5%, X7R, 0603"
D1: "LED, Blue, SMD"
D2: "LED, Green, SMD"
D3: "LED, Red, SMD"
D4: "LED, Yellow, SMD"
D5: "Diode, Schottky, 40 V, 2 A, AEC-Q101, SOD-123F"
FID1 FID2 FID3: "Fiducial mark.  There is nothing to buy or mount."
H1 H2 H3 H4: "Machine Screw, Round, #4-40 x 1/4, Nylon, Philips panhead"
H5 H6 H7 H8: "Standoff, Hex, 0.5\"L #4-40 Nylon"
J5: "Header, 100mil, 7x2, SMT"
J6: "Receptacle, D-Sub, 9 Position, R/A, TH"
J7: "Header, 100mil, 2x1, Tin, TH"
L1 L2: "Ferrite Bead, 60 ohm @ 100 MHz, 3 A, 0603"
L3: "Ferrite Bead, 220 ohm @ 100 MHz, 2 A, 0805"
L4: "Inductor, Wirewound, Ferrite, 1 µH, 1 A, 0.06 ohm, SMD"
L5: "Inductor, Shielded Drum Core, Ferrite, 1 µH, 3.6 A, 0.026 ohm, SMD"
L6: "Inductor, Shielded, 4.7 µH, 2.3 A, 0.092 ohm, SMD"
L7: "Coupled inductor, 100 µH, 0.15 A, 1.5 ohm, SMD"
LBL1: library part THT-14-423-10, "Thermal Transfer Printable Labels, 0.650\" W x 0.200\" H - 10,000 per roll"
Logo1: library part TI_Logo, "Texas Instrument Corporate Signature"
Logo2: library part Pb-Free
Logo3: library part FCC_disclaimer, "FCC_disclaimer"
Q1: "MOSFET, N-CH, 30 V, 5 A, AEC-Q101, DQK0006C (WSON-6)"
R1: "RES, 16.9, 1%, 0.1 W, 0603"
R2 R3 R4: "RES, 28.0, 1%, 0.1 W, 0603"
R5 R8 R18 R19: "RES, 100 k, 1%, 0.1 W, 0603"
R6 R7: "RES, 1.00 k, 1%, 0.1 W, 0603"
R9 R10: "RES, 10.0 k, 1%, 0.1 W, 0603"
R11 R17: "RES, 2.20 k, 1%, 0.1 W, 0603"
R12 R13: "RES, 10 k, 5%, 0.1 W, 0603"
R14 R15: "RES, 4.7 k, 5%, 0.1 W, 0603"
R16: "RES, 1.0 M, 5%, 0.063 W, 0402"
R20 R21 R22 R30 R31 R32 R33 R34: "RES, 0, 5%, 0.1 W, 0603"
R23 R24: "RES, 60.4, 1%, 0.25 W, 1206"
R25 R26: "RES, 820, 1%, 0.1 W, 0603"
R27 R28: "RES, 3.30 k, 1%, 0.1 W, 0603"
R29: "RES, 4.7, 5%, 3 W, 3W Axial resistor"
R35: "RES, 0.47, 1%, 0.125 W, 0402"
S1: "Switch, SPST-NO, Off-Mom, 12 V, SMD"
S2 S3: "Switch, SPST, 4 Pos, Top Actuated, SMD"
TP1 TP2 TP3 TP4 TP5 TP6 TP7 TP8 TP9 TP10 TP11 TP12 TP13: "1.0x1.0mm pad, square, SMD"
U1: "Piccolo Microcontroller, PAG0064A (TQFP-64)"
U2 U3: "Dual Inverter Buffer/Driver with Open-Drain Output, DCK0006A (SOT-6)"
U4: "3.5V to 36V, 1A Synchronous 2.1MHz Step-Down Converter for Automotive Applications, DSX0010A (WSON-10)"
U5: "Automotive Catalog 5V, 400mA, 4MHz Step-Up DC/DC Converter, DRV0006A (WSON-6)"
U6: "Automotive Fault Protected CAN Transceiver With Flexible Data-Rate, DRB0008F (VSON-8)"
U7: "ESD Protection Array for AC Signal Data Interface, 2 Channels, -40 to +85 degC, 3-pin SC70 (DCK), Green (RoHS & no Sb/Br)"
Y1: "Crystal, 20 MHz, 10 pF, SMD"
ZZ1: library part AssemblyNoteLabel
ZZ2 ZZ3 ZZ4: library part AssemblyNote

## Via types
v1: diameter 20, hole 7.87, Top Layer to Bottom Layer, tented both sides, 328 vias
v2: diameter 19.68, hole 7.87, Top Layer to Bottom Layer, 10 vias

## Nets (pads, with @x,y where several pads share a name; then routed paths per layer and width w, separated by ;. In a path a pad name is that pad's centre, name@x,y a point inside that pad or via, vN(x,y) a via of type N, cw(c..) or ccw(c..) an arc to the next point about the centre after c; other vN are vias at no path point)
5V_EN: R19.2 TP1.1 U1.35 U5.4 | length 1906.7
  Top Layer w7: U1.35@577.11,1693.33 v1(700.33,1693.33) ; v1(825,1720) 923,1720 1020,1817 TP1.1@1020,2240
  Top Layer w10: TP1.1@1020,2240 1072.5,2292.5 R19.2@1911.25,2292.5 ; U5.4@1911.61,2215.59 R19.2@1911.61,2292.14
  Bottom Layer w7: v1(700.33,1693.33) 798.33,1693.33 v1(825,1720)
BLUE_LED: U1.53 U2.1 | length 3755.8
  Top Layer w10: U1.53@733.6,1359.67 733.6,1296.4 835,1195 835,785 1150,470 3360,470 3443.62,553.62 3443.62,797 3469.62,823 v1(3470,823)
  Bottom Layer w10: v1(3470,823) 3470.4,823.4 U2.1@3554.71,823.4
BOOT_MODE: R27.2 S2.1 U1.61 | length 734.4
  Top Layer w10: S2.1@757.18,918.23 v1(757.18,995) v1(757.18,1227.82) ; U1.61@891.08,1359.67 891.08,1318.92 910,1300 925,1300 v1(965,1260)
  Bottom Layer w10: v1(757.18,995) 771,981.18 R27.2@771,936.14 ; v1(757.18,1227.82) 789.37,1260 v1(965,1260)
CAN_RXD: TP5.1 U1.26 U6.4 | length 2350.5
  Top Layer w7: U1.26@772.97,1810.46 772.97,1874.39 784.37,1885.79 784.37,1970 880,2065.63 880,2322 898,2340 TP5.1@1020,2340
  Top Layer w10: TP5.1@1020,2340 1057.13,2377.13 1452.6,2377.13 1485.47,2344.25 2215.75,2344.25 2285,2275 2285,2137.01 2302.01,2120 2430,2120 2444.88,2134.88 U6.4@2444.88,2148.31
CAN_STB: TP2.1 U1.34 U6.8 | length 2864.9
  Top Layer w7: v1(575,2245) 575,1945 535,1905 535,1722 543.98,1713.02 U1.34@577.11,1713.02 ; v1(700,2245) 995,2540 TP2.1@1020,2540
  Top Layer w10: TP2.1@1020,2540 1065,2495 1405,2495 1520,2380 2480,2380 2555.12,2304.88 U6.8@2555.12,2225.08
  Bottom Layer w7: v1(575,2245) v1(700,2245)
CAN_TXD: TP6.1 U1.25 U6.1 | length 2323
  Top Layer w7: U1.25@792.66,1810.46 792.66,1873.04 799.25,1879.63 799.25,1950 909.25,2060 909.25,2300 v1(910,2300) ; v1(910,2390) 960,2440 TP6.1@1020,2440
  Top Layer w10: TP6.1@1020,2440 1065,2395 1460,2395 1492.87,2362.13 2392.87,2362.13 2444.88,2310.12 U6.1@2444.88,2225.08
  Bottom Layer w7: v1(910,2300) v1(910,2390)
CANH: C26.1 J6.7 L7.3 R23.2 U7.2 | length 1304.9
  Top Layer w10: L7.3@2818.62,2233.36 2878.36,2233.36 2886.69,2241.69 R23.2@2927.91,2241.69 2961.87,2241.69 3011.16,2290.98 3240.98,2290.98 3324.68,2207.28 U7.2@3335.44,2207.28 C26.1@3419.41,2207.28 ; C26.1@3420,2206.69 3533.31,2206.69 3560,2180 3655,2180 3757.87,2077.13 3757.87,2037.6 3755,2034.72 3755,1927.64 J6.7@3681.89,1854.53
CANL: C30.1 J6.2 L7.2 R24.1 U7.1 | length 1304.9
  Top Layer w10: L7.2@2818.62,2142.81 2857.19,2142.81 2875.55,2124.45 R24.1@2927.91,2124.45 2955.55,2124.45 3005,2075 3254.34,2075 U7.1@3335.44,2156.1 3336.03,2156.69 C30.1@3420,2156.69 3465,2156.69 3478.31,2170 3542.13,2170 3550,2162.13 3647.6,2162.13 3735,2074.72 3735,2040 3730,2035 3648.64,2035 3626.57,2012.93 3626.57,1965.55 J6.2@3570.08,1909.06
DATA_RATE_SELECT1: R10.2 S2.2 U1.52 | length 505
  Top Layer w10: S2.2@707.18,918.23 v1(707.18,995) 707.18,1122.18 713.92,1128.92 U1.52@713.92,1359.67
  Bottom Layer w10: v1(707.18,995) 711.88,990.3 R10.2@711.88,936.14
DATA_RATE_SELECT2: R9.2 S2.3 U1.49 | length 624.5
  Top Layer w7: U1.49@654.86,1359.67 654.86,1303.45 556.13,1204.71 556.13,1175.29 562.79,1168.63 631.37,1168.63 644.93,1155.07 644.93,1060 657.18,1047.75 v1(657.18,995) S2.3@657.18,918.23
  Bottom Layer w7: v1@654.19,992 R9.2@654.19,936.14 R9.2@657.18,939.14
EN: R18.1 U4.7 | length 75.2
  Top Layer w10: U4.7@2044.69,1542.76 2044.69,1556.86 2085.96,1598.13 R18.1@2085.96,1600.84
